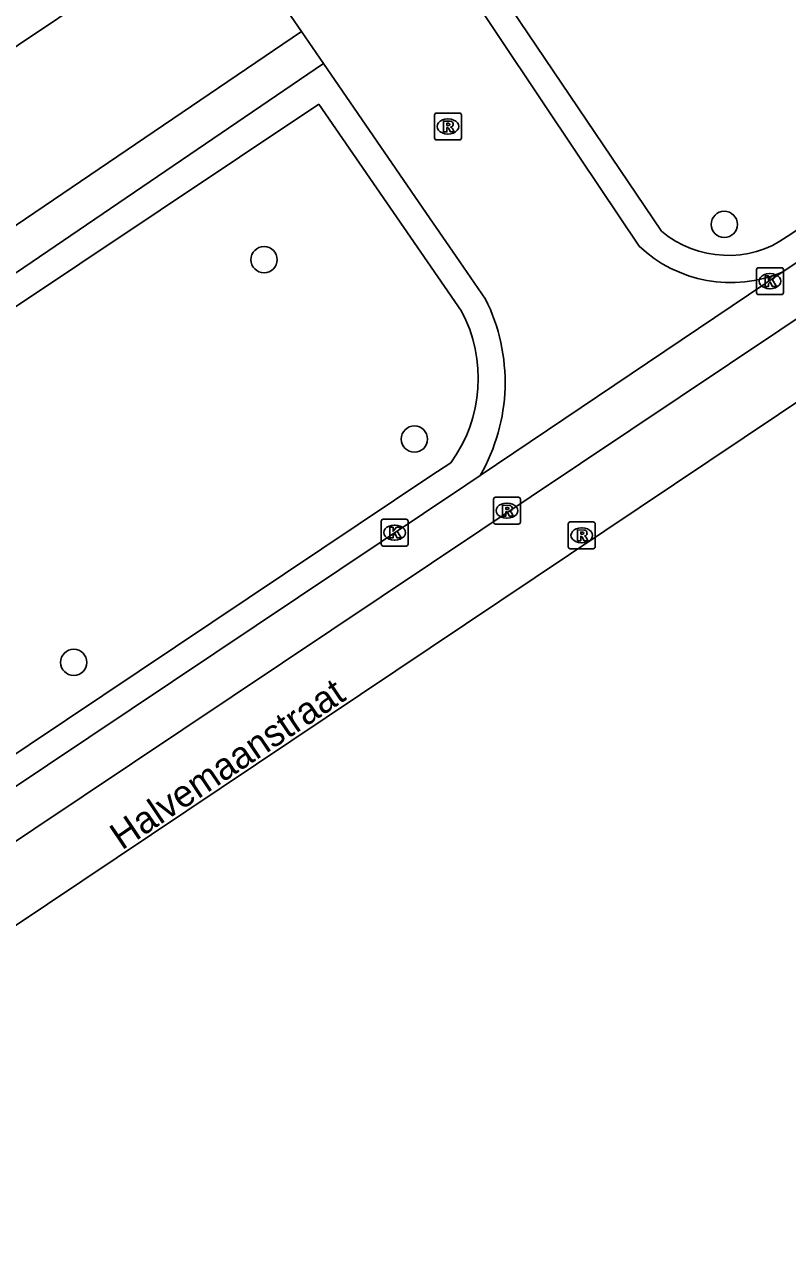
# Model space of a CAD drawing. Extents: x 158797 to 159887, y 384318 to 385255.
# Drawn here: x 159136.03 to 159164.4, y 384410.8 to 384456.56 of the extents above; entities that cross this region are included whole.
import ezdxf

# ---------------------------------------------------------------- set-up
doc = ezdxf.new("R2010")
doc.units = 0
for name, color, linetype in [('IMGEO_Boom', 7, 'Continuous'), ('IMGEO_Groenvoorziening', 7, 'Continuous'), ('IMGEO_Kolk', 7, 'Continuous'), ('IMGEO_Openbare_ruimte_label', 7, 'Continuous'), ('IMGEO_Pand', 7, 'Continuous'), ('IMGEO_Rijbaan_lokaal_gesloten', 7, 'Continuous'), ('IMGEO_Rijbaan_lokaal_open', 7, 'Continuous'), ('IMGEO_Rioolput', 7, 'Continuous'), ('IMGEO_Voetpad_open', 7, 'Continuous')]:
    doc.layers.add(name, color=color, linetype=linetype)

msp = doc.modelspace()

# ---------------------------------------------------------------- linework, layer by layer
at = {"layer": 'IMGEO_Boom'}
for centre in [(159162.058, 384449.123), (159144.94, 384447.811), (159150.53, 384441.136), (159137.86, 384432.829)]:
    msp.add_circle(centre, 0.489, dxfattribs=at)
at = {"layer": 'IMGEO_Groenvoorziening'}
for points in [[(159159.718, 384448.873), (159153.52, 384458.067), (159165.961, 384466.384), (159167.121, 384464.672), (159171.21, 384467.315), (159177.724, 384457.553), (159164.401, 384448.67)], [(159109.388, 384418.603), (159109.094, 384421.643), (159108.491, 384427.893), (159146.977, 384453.593)], [(159146.977, 384453.593), (159152.28, 384445.899)], [(159151.885, 384440.258), (159151.148, 384439.765), (159114.499, 384415.224), (159113.146, 384414.855)]]:
    msp.add_lwpolyline(points, dxfattribs=at)
for centre, radius, start, end in [((159162.191, 384451.801), 3.832, 229.8158, 305.22), ((159147.584, 384443.394), 5.323, 323.9097, 28.0794)]:
    msp.add_arc(centre, radius, start, end, dxfattribs=at)
at = {"layer": 'IMGEO_Kolk'}
for p, q in [((159163.256, 384446.585), (159163.256, 384447.437)), ((159163.331, 384447.511), (159164.183, 384447.511)), ((159163.744, 384447.291), (159163.769, 384447.291)), ((159164.257, 384447.437), (159164.257, 384446.585)), ((159163.767, 384446.731), (159163.742, 384446.731)), ((159164.183, 384446.511), (159163.331, 384446.511)), ((159149.296, 384437.23), (159149.296, 384438.082)), ((159149.371, 384438.156), (159150.223, 384438.156)), ((159150.297, 384438.082), (159150.297, 384437.23)), ((159149.784, 384437.936), (159149.809, 384437.936)), ((159150.223, 384437.156), (159149.371, 384437.156)), ((159149.807, 384437.376), (159149.782, 384437.376))]:
    msp.add_line(p, q, dxfattribs=at)
for points in [[(159163.256, 384446.585), (159163.256, 384447.437)], [(159163.331, 384447.511), (159164.183, 384447.511)], [(159163.577, 384447.211), (159163.7, 384447.211), (159163.7, 384447.06), (159163.83, 384447.211), (159163.994, 384447.211), (159163.848, 384447.06), (159164.001, 384446.811), (159163.849, 384446.811), (159163.764, 384446.975), (159163.7, 384446.908), (159163.7, 384446.811), (159163.577, 384446.811), (159163.577, 384447.211)], [(159164.257, 384447.437), (159164.257, 384446.585)], [(159164.183, 384446.511), (159163.331, 384446.511)], [(159149.296, 384437.23), (159149.296, 384438.082)], [(159149.371, 384438.156), (159150.223, 384438.156)], [(159150.297, 384438.082), (159150.297, 384437.23)], [(159149.617, 384437.856), (159149.74, 384437.856), (159149.74, 384437.705), (159149.87, 384437.856), (159150.034, 384437.856), (159149.888, 384437.705), (159150.041, 384437.456), (159149.889, 384437.456), (159149.804, 384437.62), (159149.74, 384437.553), (159149.74, 384437.456), (159149.617, 384437.456), (159149.617, 384437.856)], [(159150.223, 384437.156), (159149.371, 384437.156)]]:
    msp.add_lwpolyline(points, dxfattribs=at)
for centre, start, end in [((159163.333, 384447.435), 91.552, 178.448), ((159163.333, 384447.435), 91.552, 178.448), ((159164.181, 384447.435), 1.552, 88.448), ((159164.181, 384447.435), 1.552, 88.448), ((159163.333, 384446.587), 181.552, 268.448), ((159163.333, 384446.587), 181.552, 268.448), ((159164.181, 384446.587), 271.552, 358.448), ((159164.181, 384446.587), 271.552, 358.448), ((159149.373, 384438.08), 91.552, 178.448), ((159149.373, 384438.08), 91.552, 178.448), ((159150.221, 384438.08), 1.552, 88.448), ((159150.221, 384438.08), 1.552, 88.448), ((159149.373, 384437.232), 181.552, 268.448), ((159149.373, 384437.232), 181.552, 268.448), ((159150.221, 384437.232), 271.552, 358.448), ((159150.221, 384437.232), 271.552, 358.448)]:
    msp.add_arc(centre, 0.0765, start, end, dxfattribs=at)
for centre, major_axis, ratio, start_param, end_param in [((159163.743, 384447.011), (-0.387, 0.002), 0.722429, 4.712389, 7.853982), ((159163.768, 384447.011), (-0.39, 0.002), 0.717154, 1.570796, 4.712389), ((159149.783, 384437.656), (-0.387, 0.002), 0.722429, 4.712389, 7.853982), ((159149.808, 384437.656), (-0.39, 0.002), 0.717154, 1.570796, 4.712389)]:
    msp.add_ellipse(centre, major_axis=major_axis, ratio=ratio, start_param=start_param, end_param=end_param, dxfattribs=at)
at = {"layer": 'IMGEO_Pand'}
msp.add_lwpolyline([(159105.622, 384435.536), (159134.297, 384454.798), (159140.265, 384458.806), (159139.961, 384459.26)], dxfattribs=at)
at = {"layer": 'IMGEO_Rijbaan_lokaal_gesloten'}
for points in [[(159270.461, 384513.33), (159268.841, 384512.562), (159250.873, 384502.69), (159237.802, 384494.419), (159214.07, 384478.627), (159115.99, 384412.992)], [(159179.109, 384457.279), (159164.212, 384447.342)], [(159164.212, 384447.342), (159152.977, 384439.786)], [(159117.415, 384410.802), (159170.564, 384446.405), (159170.651, 384446.275), (159170.651, 384446.275)], [(159152.977, 384439.786), (159152.441, 384439.427), (159115.055, 384414.393)]]:
    msp.add_lwpolyline(points, dxfattribs=at)
at = {"layer": 'IMGEO_Rijbaan_lokaal_open'}
for points in [[(159142.934, 384461.253), (159146.329, 384456.299)], [(159158.887, 384448.317), (159156.675, 384451.624), (159152.167, 384458.365)], [(159146.329, 384456.299), (159147.152, 384455.106)], [(159147.152, 384455.106), (159151.122, 384449.331), (159151.815, 384448.322), (159153.174, 384446.346)]]:
    msp.add_lwpolyline(points, dxfattribs=at)
for centre, radius, start, end in [((159162.299, 384451.923), 4.965, 226.5845, 292.6638), ((159146.98, 384443.249), 6.925, 329.9936, 26.5662)]:
    msp.add_arc(centre, radius, start, end, dxfattribs=at)
at = {"layer": 'IMGEO_Rioolput'}
for p, q in [((159151.278, 384452.34), (159151.278, 384453.192)), ((159151.353, 384453.266), (159152.205, 384453.266)), ((159152.279, 384453.192), (159152.279, 384452.34)), ((159151.766, 384453.046), (159151.791, 384453.046)), ((159152.205, 384452.266), (159151.353, 384452.266)), ((159151.789, 384452.486), (159151.764, 384452.486)), ((159153.549, 384438.973), (159154.401, 384438.973)), ((159153.474, 384438.047), (159153.474, 384438.899)), ((159153.962, 384438.753), (159153.987, 384438.753)), ((159154.475, 384438.899), (159154.475, 384438.047)), ((159153.985, 384438.193), (159153.96, 384438.193)), ((159156.33, 384438.055), (159157.182, 384438.055)), ((159154.401, 384437.973), (159153.549, 384437.973)), ((159156.255, 384437.129), (159156.255, 384437.981)), ((159156.743, 384437.835), (159156.768, 384437.835)), ((159157.256, 384437.981), (159157.256, 384437.129)), ((159156.766, 384437.275), (159156.741, 384437.275)), ((159157.182, 384437.055), (159156.33, 384437.055))]:
    msp.add_line(p, q, dxfattribs=at)
for points in [[(159151.278, 384452.34), (159151.278, 384453.192)], [(159151.353, 384453.266), (159152.205, 384453.266)], [(159152.279, 384453.192), (159152.279, 384452.34)], [(159151.867, 384452.964), (159151.615, 384452.966), (159151.615, 384452.566)], [(159151.615, 384452.566), (159151.739, 384452.566), (159151.739, 384452.728), (159151.75, 384452.728)], [(159151.793, 384452.885), (159151.739, 384452.885), (159151.739, 384452.804)], [(159151.739, 384452.804), (159151.791, 384452.804)], [(159151.797, 384452.699), (159151.868, 384452.566), (159152.008, 384452.566), (159151.943, 384452.692)], [(159152.205, 384452.266), (159151.353, 384452.266)], [(159153.549, 384438.973), (159154.401, 384438.973)], [(159153.474, 384438.047), (159153.474, 384438.899)], [(159154.063, 384438.671), (159153.811, 384438.673), (159153.811, 384438.273)], [(159153.989, 384438.592), (159153.935, 384438.592), (159153.935, 384438.511)], [(159153.935, 384438.511), (159153.987, 384438.511)], [(159154.475, 384438.899), (159154.475, 384438.047)], [(159153.811, 384438.273), (159153.935, 384438.273), (159153.935, 384438.435), (159153.946, 384438.435)], [(159153.993, 384438.406), (159154.064, 384438.273), (159154.204, 384438.273), (159154.139, 384438.399)], [(159156.33, 384438.055), (159157.182, 384438.055)], [(159154.401, 384437.973), (159153.549, 384437.973)], [(159156.255, 384437.129), (159156.255, 384437.981)], [(159156.844, 384437.753), (159156.592, 384437.755), (159156.592, 384437.355)], [(159156.77, 384437.674), (159156.716, 384437.674), (159156.716, 384437.593)], [(159156.716, 384437.593), (159156.768, 384437.593)], [(159157.256, 384437.981), (159157.256, 384437.129)], [(159156.592, 384437.355), (159156.716, 384437.355), (159156.716, 384437.517), (159156.727, 384437.517)], [(159156.774, 384437.488), (159156.845, 384437.355), (159156.985, 384437.355), (159156.92, 384437.481)], [(159157.182, 384437.055), (159156.33, 384437.055)]]:
    msp.add_lwpolyline(points, dxfattribs=at)
for centre, radius, start, end in [((159151.355, 384453.19), 0.0765, 91.552, 178.448), ((159151.355, 384453.19), 0.0765, 91.552, 178.448), ((159152.203, 384453.19), 0.0765, 1.552, 88.448), ((159152.203, 384453.19), 0.0765, 1.552, 88.448), ((159151.749, 384452.675), 0.0533, 26.0293, 88.6989), ((159151.775, 384452.993), 0.19, 274.7715, 282.9687), ((159151.799, 384452.789), 0.0964, 77.0061, 93.1865), ((159151.813, 384452.846), 0.0378, 276.6634, 79.6772), ((159151.866, 384452.854), 0.109, 350.3612, 89.416), ((159151.864, 384452.854), 0.112, 277.5842, 350.9817), ((159151.848, 384452.639), 0.108, 29.5134, 73.7905), ((159151.355, 384452.342), 0.0765, 181.552, 268.448), ((159151.355, 384452.342), 0.0765, 181.552, 268.448), ((159152.203, 384452.342), 0.0765, 271.552, 358.448), ((159152.203, 384452.342), 0.0765, 271.552, 358.448), ((159153.551, 384438.897), 0.0765, 91.552, 178.448), ((159153.551, 384438.897), 0.0765, 91.552, 178.448), ((159154.399, 384438.897), 0.0765, 1.552, 88.448), ((159154.399, 384438.897), 0.0765, 1.552, 88.448), ((159153.971, 384438.7), 0.19, 274.7715, 282.9687), ((159153.995, 384438.496), 0.0964, 77.0061, 93.1865), ((159154.009, 384438.553), 0.0378, 276.6634, 79.6772), ((159154.062, 384438.561), 0.109, 350.3612, 89.416), ((159154.06, 384438.561), 0.112, 277.5842, 350.9817), ((159153.551, 384438.049), 0.0765, 181.552, 268.448), ((159153.551, 384438.049), 0.0765, 181.552, 268.448), ((159153.945, 384438.382), 0.0533, 26.0293, 88.6989), ((159154.044, 384438.346), 0.108, 29.5134, 73.7905), ((159154.399, 384438.049), 0.0765, 271.552, 358.448), ((159154.399, 384438.049), 0.0765, 271.552, 358.448), ((159156.332, 384437.979), 0.0765, 91.552, 178.448), ((159156.332, 384437.979), 0.0765, 91.552, 178.448), ((159157.18, 384437.979), 0.0765, 1.552, 88.448), ((159157.18, 384437.979), 0.0765, 1.552, 88.448), ((159156.752, 384437.782), 0.19, 274.7715, 282.9687), ((159156.776, 384437.578), 0.0964, 77.0061, 93.1865), ((159156.79, 384437.635), 0.0378, 276.6634, 79.6772), ((159156.843, 384437.643), 0.109, 350.3612, 89.416), ((159156.841, 384437.643), 0.112, 277.5842, 350.9817), ((159156.332, 384437.131), 0.0765, 181.552, 268.448), ((159156.332, 384437.131), 0.0765, 181.552, 268.448), ((159156.726, 384437.464), 0.0533, 26.0293, 88.6989), ((159156.825, 384437.428), 0.108, 29.5134, 73.7905), ((159157.18, 384437.131), 0.0765, 271.552, 358.448), ((159157.18, 384437.131), 0.0765, 271.552, 358.448)]:
    msp.add_arc(centre, radius, start, end, dxfattribs=at)
for centre, major_axis, ratio, start_param, end_param in [((159151.765, 384452.766), (-0.387, 0.002), 0.722429, 4.712389, 7.853982), ((159151.79, 384452.766), (-0.39, 0.002), 0.717154, 1.570796, 4.712389), ((159153.961, 384438.473), (-0.387, 0.002), 0.722429, 4.712389, 7.853982), ((159153.986, 384438.473), (-0.39, 0.002), 0.717154, 1.570796, 4.712389), ((159156.742, 384437.555), (-0.387, 0.002), 0.722429, 4.712389, 7.853982), ((159156.767, 384437.555), (-0.39, 0.002), 0.717154, 1.570796, 4.712389)]:
    msp.add_ellipse(centre, major_axis=major_axis, ratio=ratio, start_param=start_param, end_param=end_param, dxfattribs=at)
at = {"layer": 'IMGEO_Voetpad_open'}
for points in [[(159106.875, 384429.844), (159133.657, 384447.711), (159146.329, 384456.299)], [(159107.339, 384428.325), (159133.348, 384445.716), (159147.152, 384455.106)]]:
    msp.add_lwpolyline(points, dxfattribs=at)

# ---------------------------------------------------------------- texts
at = {"layer": 'IMGEO_Openbare_ruimte_label'}
msp.add_text('Halvemaanstraat', height=1, rotation=33.9125, dxfattribs=at).set_placement((159139.651, 384425.825))

doc.saveas('drawing.dxf')
